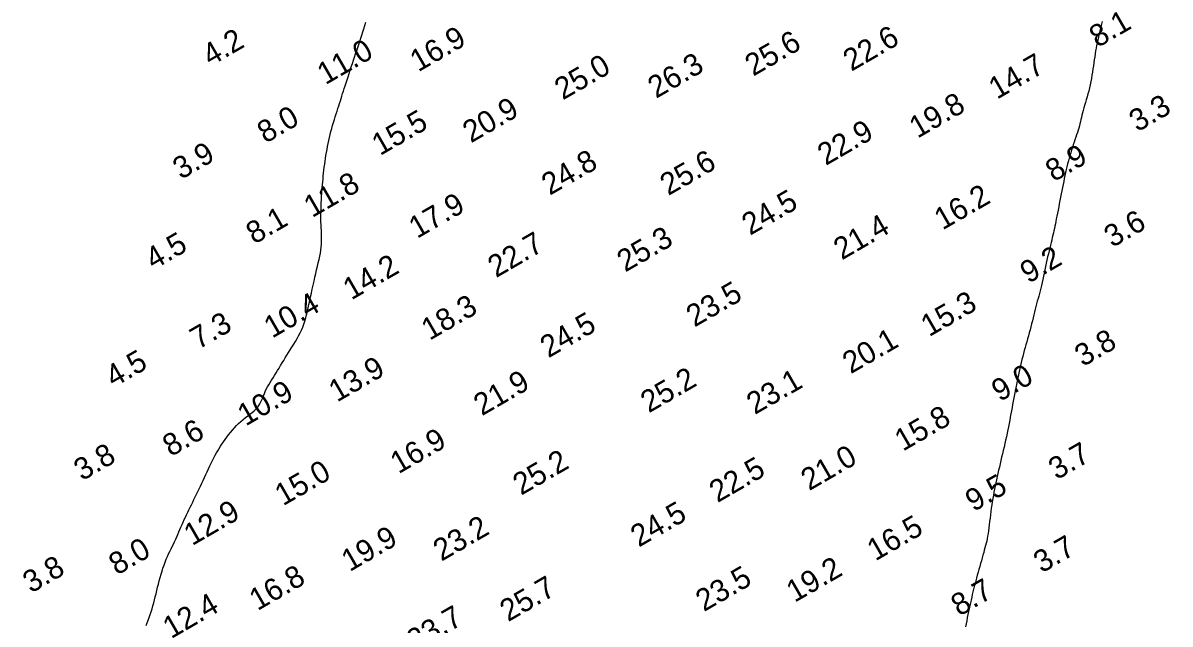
# Model space of a CAD drawing. Extents: x 3024098 to 3056816, y 418252 to 509144.
# Drawn here: x 3026706.3 to 3026967.6, y 421991.1 to 422128 of the extents above; entities that cross this region are included whole.
import ezdxf

# ---------------------------------------------------------------- set-up
doc = ezdxf.new("R2010")
doc.units = 0
doc.layers.add('V-CHAN-CONT-EL10', color=7, linetype='Continuous')
doc.layers.add('V-TOPO-SOUN-0911', color=7, linetype='Continuous')

msp = doc.modelspace()

# ---------------------------------------------------------------- linework, layer by layer
at = {"layer": 'V-CHAN-CONT-EL10'}
for points in [[(3026952.18, 422128.4), (3026952.02, 422127.75), (3026951.87, 422127.13), (3026951.73, 422126.52), (3026951.58, 422125.92), (3026951.44, 422125.32), (3026951.31, 422124.73), (3026951.18, 422124.13), (3026951.05, 422123.53), (3026950.93, 422122.91), (3026950.81, 422122.29), (3026950.7, 422121.65), (3026950.59, 422121), (3026950.48, 422120.34), (3026950.38, 422119.67), (3026950.28, 422118.98), (3026950.18, 422118.28), (3026950.07, 422117.57), (3026949.96, 422116.85), (3026949.85, 422116.12), (3026949.73, 422115.4), (3026949.6, 422114.67), (3026949.46, 422113.95), (3026949.31, 422113.24), (3026949.13, 422112.53), (3026948.95, 422111.85), (3026948.76, 422111.17), (3026948.56, 422110.51), (3026948.37, 422109.88), (3026948.18, 422109.26), (3026948, 422108.66), (3026947.84, 422108.09), (3026947.7, 422107.55), (3026947.57, 422107.03), (3026947.45, 422106.53), (3026947.34, 422106.03), (3026947.23, 422105.55), (3026947.11, 422105.06), (3026946.99, 422104.58), (3026946.86, 422104.08), (3026946.7, 422103.58), (3026946.54, 422103.06), (3026946.36, 422102.53), (3026946.17, 422101.98), (3026945.98, 422101.43), (3026945.78, 422100.86), (3026945.59, 422100.28), (3026945.39, 422099.69), (3026945.2, 422099.09), (3026945.01, 422098.48), (3026944.83, 422097.86), (3026944.65, 422097.23), (3026944.48, 422096.59), (3026944.32, 422095.95), (3026944.15, 422095.29), (3026944, 422094.63), (3026943.85, 422093.97), (3026943.7, 422093.3), (3026943.56, 422092.62), (3026943.42, 422091.93), (3026943.28, 422091.24), (3026943.14, 422090.53), (3026943, 422089.82), (3026942.86, 422089.09), (3026942.71, 422088.35), (3026942.57, 422087.6), (3026942.42, 422086.86), (3026942.28, 422086.12), (3026942.14, 422085.4), (3026942, 422084.71), (3026941.87, 422084.04), (3026941.74, 422083.41), (3026941.63, 422082.81), (3026941.52, 422082.26), (3026941.41, 422081.73), (3026941.3, 422081.21), (3026941.19, 422080.7), (3026941.08, 422080.2), (3026940.96, 422079.68), (3026940.83, 422079.14), (3026940.7, 422078.58), (3026940.56, 422077.99), (3026940.4, 422077.38), (3026940.25, 422076.75), (3026940.09, 422076.09), (3026939.93, 422075.41), (3026939.76, 422074.72), (3026939.6, 422074.01), (3026939.44, 422073.28), (3026939.29, 422072.54), (3026939.13, 422071.8), (3026938.98, 422071.06), (3026938.83, 422070.33), (3026938.68, 422069.62), (3026938.52, 422068.92), (3026938.37, 422068.25), (3026938.21, 422067.61), (3026938.05, 422066.99), (3026937.89, 422066.4), (3026937.73, 422065.81), (3026937.57, 422065.23), (3026937.4, 422064.64), (3026937.24, 422064.05), (3026937.08, 422063.45), (3026936.93, 422062.82), (3026936.77, 422062.17), (3026936.61, 422061.52), (3026936.45, 422060.84), (3026936.29, 422060.16), (3026936.12, 422059.48), (3026935.95, 422058.79), (3026935.77, 422058.11), (3026935.59, 422057.43), (3026935.4, 422056.75), (3026935.21, 422056.08), (3026935.01, 422055.41), (3026934.82, 422054.74), (3026934.63, 422054.07), (3026934.44, 422053.4), (3026934.26, 422052.73), (3026934.08, 422052.06), (3026933.92, 422051.38), (3026933.75, 422050.7), (3026933.6, 422050.01), (3026933.44, 422049.32), (3026933.29, 422048.61), (3026933.13, 422047.9), (3026932.98, 422047.17), (3026932.83, 422046.43), (3026932.67, 422045.68), (3026932.52, 422044.92), (3026932.37, 422044.16), (3026932.22, 422043.39), (3026932.07, 422042.63), (3026931.93, 422041.88), (3026931.79, 422041.13), (3026931.65, 422040.4), (3026931.52, 422039.67), (3026931.39, 422038.95), (3026931.25, 422038.24), (3026931.12, 422037.52), (3026930.98, 422036.79), (3026930.84, 422036.06), (3026930.69, 422035.31), (3026930.53, 422034.55), (3026930.37, 422033.77), (3026930.19, 422032.99), (3026930.02, 422032.2), (3026929.84, 422031.41), (3026929.66, 422030.63), (3026929.48, 422029.85), (3026929.29, 422029.08), (3026929.12, 422028.32), (3026928.94, 422027.58), (3026928.77, 422026.85), (3026928.6, 422026.12), (3026928.43, 422025.41), (3026928.27, 422024.69), (3026928.12, 422023.98), (3026927.96, 422023.27), (3026927.81, 422022.57), (3026927.67, 422021.85), (3026927.53, 422021.14), (3026927.4, 422020.42), (3026927.27, 422019.7), (3026927.15, 422018.97), (3026927.04, 422018.23), (3026926.93, 422017.48), (3026926.83, 422016.72), (3026926.73, 422015.96), (3026926.64, 422015.2), (3026926.55, 422014.45), (3026926.47, 422013.72), (3026926.38, 422013.02), (3026926.29, 422012.34), (3026926.19, 422011.7), (3026926.09, 422011.1), (3026925.99, 422010.54), (3026925.88, 422010.01), (3026925.75, 422009.49), (3026925.63, 422008.98), (3026925.49, 422008.46), (3026925.34, 422007.93), (3026925.19, 422007.37), (3026925.02, 422006.79), (3026924.84, 422006.17), (3026924.66, 422005.53), (3026924.47, 422004.88), (3026924.29, 422004.22), (3026924.1, 422003.55), (3026923.91, 422002.88), (3026923.73, 422002.22), (3026923.55, 422001.57), (3026923.39, 422000.94), (3026923.22, 422000.31), (3026923.06, 421999.68), (3026922.91, 421999.06), (3026922.75, 421998.44), (3026922.6, 421997.82), (3026922.46, 421997.19), (3026922.31, 421996.55), (3026922.16, 421995.91), (3026922.01, 421995.26), (3026921.87, 421994.6), (3026921.73, 421993.93), (3026921.59, 421993.25), (3026921.46, 421992.55), (3026921.33, 421991.85), (3026921.2, 421991.14), (3026921.08, 421990.42)], [(3026734.38, 421990.78), (3026734.63, 421991.38), (3026734.87, 421992), (3026735.11, 421992.62), (3026735.34, 421993.26), (3026735.56, 421993.9), (3026735.77, 421994.56), (3026735.96, 421995.23), (3026736.15, 421995.91), (3026736.33, 421996.6), (3026736.5, 421997.3), (3026736.68, 421998.01), (3026736.85, 421998.73), (3026737.03, 421999.46), (3026737.22, 422000.2), (3026737.41, 422000.94), (3026737.61, 422001.68), (3026737.81, 422002.42), (3026738.03, 422003.14), (3026738.25, 422003.85), (3026738.49, 422004.54), (3026738.73, 422005.21), (3026738.99, 422005.85), (3026739.26, 422006.46), (3026739.53, 422007.06), (3026739.8, 422007.64), (3026740.08, 422008.2), (3026740.35, 422008.76), (3026740.62, 422009.31), (3026740.89, 422009.86), (3026741.14, 422010.41), (3026741.39, 422010.96), (3026741.64, 422011.52), (3026741.88, 422012.08), (3026742.11, 422012.64), (3026742.35, 422013.19), (3026742.6, 422013.75), (3026742.84, 422014.31), (3026743.1, 422014.88), (3026743.35, 422015.44), (3026743.62, 422016), (3026743.89, 422016.56), (3026744.16, 422017.13), (3026744.44, 422017.7), (3026744.72, 422018.28), (3026745.01, 422018.86), (3026745.29, 422019.45), (3026745.59, 422020.05), (3026745.88, 422020.65), (3026746.18, 422021.27), (3026746.47, 422021.89), (3026746.77, 422022.52), (3026747.07, 422023.16), (3026747.38, 422023.81), (3026747.68, 422024.47), (3026747.98, 422025.14), (3026748.29, 422025.8), (3026748.6, 422026.47), (3026748.9, 422027.12), (3026749.21, 422027.76), (3026749.51, 422028.38), (3026749.81, 422028.97), (3026750.11, 422029.53), (3026750.41, 422030.07), (3026750.72, 422030.59), (3026751.03, 422031.1), (3026751.35, 422031.6), (3026751.68, 422032.1), (3026752.03, 422032.6), (3026752.4, 422033.11), (3026752.78, 422033.64), (3026753.19, 422034.17), (3026753.61, 422034.71), (3026754.05, 422035.25), (3026754.51, 422035.78), (3026754.99, 422036.29), (3026755.48, 422036.79), (3026755.99, 422037.26), (3026756.5, 422037.71), (3026757.03, 422038.12), (3026757.55, 422038.52), (3026758.05, 422038.91), (3026758.54, 422039.29), (3026758.99, 422039.67), (3026759.4, 422040.06), (3026759.77, 422040.45), (3026760.08, 422040.86), (3026760.34, 422041.29), (3026760.56, 422041.73), (3026760.77, 422042.18), (3026760.96, 422042.65), (3026761.14, 422043.12), (3026761.34, 422043.61), (3026761.55, 422044.1), (3026761.79, 422044.6), (3026762.06, 422045.1), (3026762.36, 422045.62), (3026762.67, 422046.14), (3026762.99, 422046.66), (3026763.33, 422047.2), (3026763.67, 422047.74), (3026764.01, 422048.29), (3026764.36, 422048.85), (3026764.7, 422049.41), (3026765.04, 422049.99), (3026765.39, 422050.57), (3026765.75, 422051.16), (3026766.1, 422051.75), (3026766.47, 422052.35), (3026766.85, 422052.97), (3026767.23, 422053.58), (3026767.62, 422054.2), (3026768.02, 422054.83), (3026768.4, 422055.47), (3026768.78, 422056.11), (3026769.14, 422056.76), (3026769.48, 422057.42), (3026769.79, 422058.08), (3026770.07, 422058.75), (3026770.32, 422059.43), (3026770.55, 422060.12), (3026770.76, 422060.83), (3026770.95, 422061.56), (3026771.14, 422062.32), (3026771.32, 422063.1), (3026771.5, 422063.91), (3026771.68, 422064.76), (3026771.87, 422065.62), (3026772.06, 422066.51), (3026772.26, 422067.41), (3026772.45, 422068.31), (3026772.65, 422069.21), (3026772.85, 422070.1), (3026773.05, 422070.96), (3026773.25, 422071.8), (3026773.44, 422072.61), (3026773.63, 422073.4), (3026773.81, 422074.16), (3026773.96, 422074.9), (3026774.1, 422075.61), (3026774.22, 422076.3), (3026774.3, 422076.97), (3026774.35, 422077.62), (3026774.38, 422078.26), (3026774.39, 422078.89), (3026774.37, 422079.51), (3026774.35, 422080.14), (3026774.32, 422080.77), (3026774.29, 422081.41), (3026774.26, 422082.07), (3026774.24, 422082.75), (3026774.23, 422083.45), (3026774.23, 422084.16), (3026774.24, 422084.88), (3026774.25, 422085.61), (3026774.27, 422086.33), (3026774.3, 422087.05), (3026774.34, 422087.77), (3026774.38, 422088.46), (3026774.42, 422089.15), (3026774.47, 422089.83), (3026774.52, 422090.5), (3026774.58, 422091.16), (3026774.64, 422091.82), (3026774.71, 422092.48), (3026774.77, 422093.15), (3026774.84, 422093.81), (3026774.92, 422094.48), (3026775, 422095.16), (3026775.08, 422095.83), (3026775.17, 422096.51), (3026775.27, 422097.19), (3026775.37, 422097.87), (3026775.48, 422098.55), (3026775.61, 422099.24), (3026775.74, 422099.92), (3026775.88, 422100.6), (3026776.02, 422101.29), (3026776.18, 422101.97), (3026776.35, 422102.65), (3026776.52, 422103.33), (3026776.7, 422104.01), (3026776.89, 422104.69), (3026777.09, 422105.36), (3026777.29, 422106.03), (3026777.49, 422106.68), (3026777.7, 422107.32), (3026777.9, 422107.95), (3026778.09, 422108.56), (3026778.29, 422109.15), (3026778.47, 422109.72), (3026778.65, 422110.28), (3026778.82, 422110.83), (3026778.99, 422111.38), (3026779.17, 422111.93), (3026779.35, 422112.5), (3026779.54, 422113.1), (3026779.74, 422113.72), (3026779.95, 422114.38), (3026780.18, 422115.07), (3026780.41, 422115.79), (3026780.65, 422116.52), (3026780.9, 422117.27), (3026781.14, 422118.03), (3026781.39, 422118.78), (3026781.64, 422119.53), (3026781.89, 422120.26), (3026782.13, 422120.99), (3026782.37, 422121.71), (3026782.61, 422122.42), (3026782.85, 422123.13), (3026783.08, 422123.84), (3026783.32, 422124.55), (3026783.55, 422125.27), (3026783.78, 422126), (3026784.01, 422126.73), (3026784.23, 422127.47), (3026784.46, 422128.22)]]:
    msp.add_lwpolyline(points, dxfattribs=at)

# ---------------------------------------------------------------- texts
at = {"layer": 'V-TOPO-SOUN-0911'}
for s, p in [('8.1', (3026951.13, 422122.3)), ('4.2', (3026749.08, 422118.08)), ('16.9 ', (3026796.39, 422116.77)), ('25.6 ', (3026872.7, 422115.79)), ('22.6 ', (3026895.05, 422116.9)), ('11.0 ', (3026775.25, 422113.84)), ('25.0 ', (3026829.32, 422110.37)), ('26.3 ', (3026850.56, 422110.73)), ('14.7 ', (3026928.22, 422110.53)), ('20.9 ', (3026808.4, 422100.59)), ('19.8 ', (3026910.11, 422101.64)), ('3.3', (3026960.2, 422103.09)), ('8.0', (3026761.6, 422100.5)), ('15.5 ', (3026787.69, 422097.7)), ('22.9 ', (3026889.21, 422095.44)), ('3.9', (3026742.36, 422092.26)), ('8.9', (3026941.14, 422091.74)), ('24.8 ', (3026826.35, 422088.65)), ('25.6 ', (3026853.35, 422088.59)), ('11.8 ', (3026772.21, 422083.56)), ('17.9 ', (3026796.13, 422078.81)), ('24.5 ', (3026871.97, 422079.53)), ('16.2 ', (3026915.81, 422080.74)), ('8.1', (3026759.04, 422077.52)), ('21.4 ', (3026892.88, 422073.92)), ('3.6', (3026954.49, 422076.75)), ('25.3 ', (3026843.54, 422071.16)), ('4.5', (3026736.11, 422071.69)), ('22.7 ', (3026814.11, 422069.88)), ('9.2', (3026935.37, 422068.58)), ('14.2 ', (3026781.14, 422064.8)), ('23.5 ', (3026859.31, 422058.63)), ('10.4 ', (3026763.12, 422056.1)), ('18.3 ', (3026798.98, 422055.61)), ('15.3 ', (3026912.76, 422056.43)), ('7.3', (3026746.29, 422053.55)), ('24.5 ', (3026826.04, 422051.61)), ('20.1 ', (3026894.9, 422047.98)), ('3.8', (3026947.8, 422049.61)), ('4.5', (3026727.02, 422044.89)), ('13.9 ', (3026777.89, 422041.54)), ('9.0', (3026928.86, 422041.64)), ('21.9 ', (3026810.89, 422038.42)), ('25.2 ', (3026848.92, 422039.08)), ('23.1 ', (3026873.05, 422038.7)), ('10.9 ', (3026757.09, 422036.09)), ('15.8 ', (3026906.79, 422030.35)), ('8.6', (3026740.03, 422029.11)), ('16.9 ', (3026791.9, 422025.2)), ('3.8', (3026719.82, 422023.6)), ('21.0 ', (3026885.45, 422021.36)), ('3.7', (3026941.83, 422023.83)), ('25.2 ', (3026819.82, 422020.31)), ('22.5 ', (3026864.56, 422018.64)), ('15.0 ', (3026765.6, 422017.91)), ('9.5', (3026922.89, 422016.58)), ('12.9 ', (3026744.88, 422008.83)), ('24.5 ', (3026846.64, 422008.5)), ('23.2 ', (3026801.67, 422005.28)), ('16.5 ', (3026900.52, 422005.35)), ('19.9 ', (3026780.78, 422002.92)), ('3.7', (3026938.42, 422002.6)), ('8.0', (3026727.77, 422002.11)), ('3.8', (3026708.2, 421998.01)), ('19.2 ', (3026882.12, 421995.9)), ('16.8 ', (3026759.78, 421994.03)), ('23.5 ', (3026861.47, 421993.8)), ('25.7 ', (3026816.86, 421991.5)), ('8.7', (3026919.62, 421992.76)), ('12.4 ', (3026740.09, 421987.63)), ('23.7 ', (3026795.67, 421984.75))]:
    msp.add_text(s, height=5, rotation=30, dxfattribs=at).set_placement(p)

doc.saveas('drawing.dxf')
